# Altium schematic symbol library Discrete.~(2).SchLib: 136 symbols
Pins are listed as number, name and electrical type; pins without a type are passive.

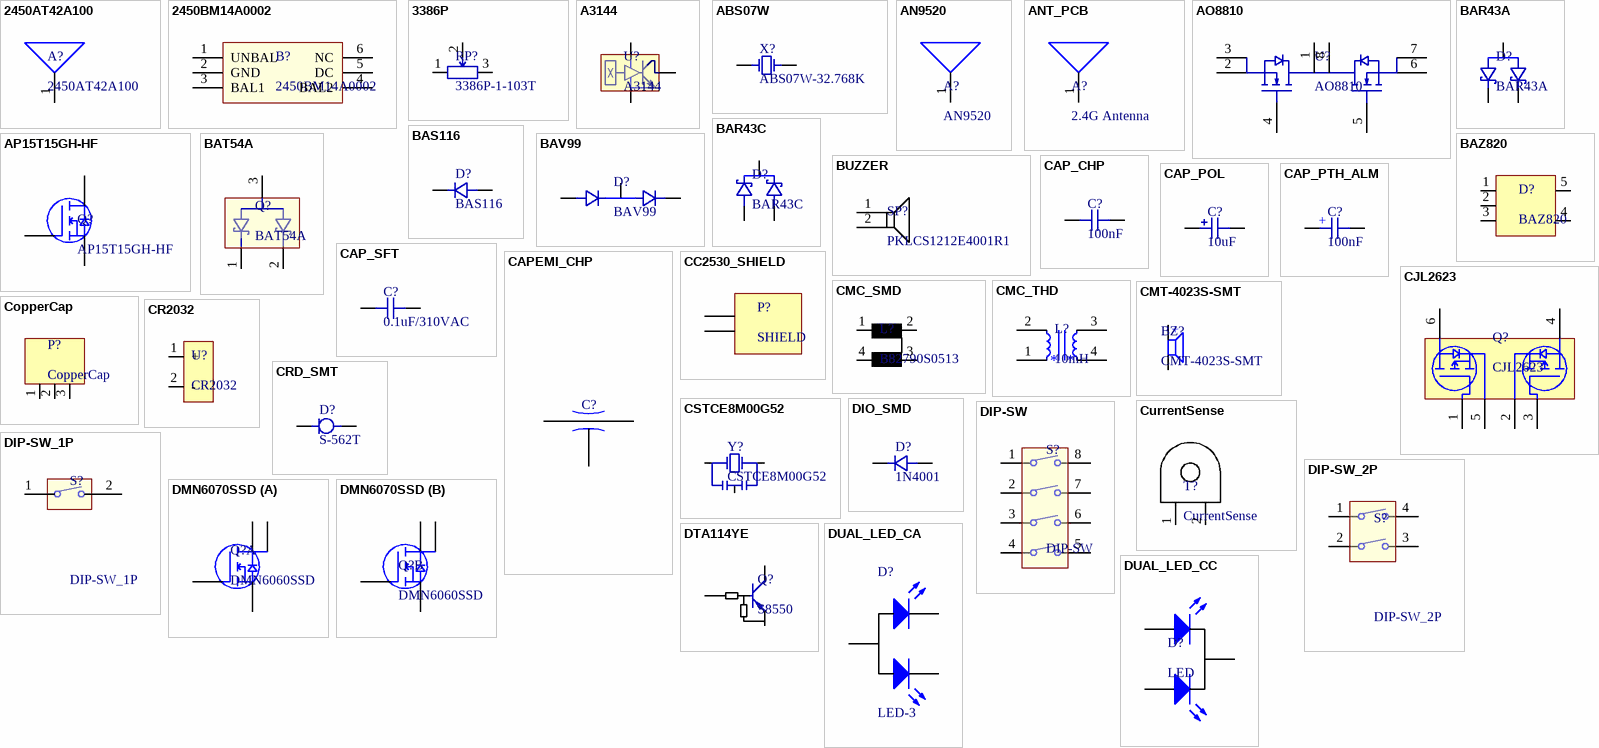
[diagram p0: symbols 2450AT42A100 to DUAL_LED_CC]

## 2450AT42A100
designator A?
2.4G Ceramic Chip Antenna
footprint 2450AT42A100
pins: 1

## 2450BM14A0002
designator B?
Impedance Matched Balun Filter Integrated Passive for   Nordic’s nRF24L01 and nRF24L01+ Chipsets
footprint 2450BM14A0002 (Impedance Matched Balun Filter Integrated Passive for   Nordic’s nRF24L01 and nRF24L01+ Chipsets)
pins: 1 UNBAL, 2 GND (power), 3 BAL1, 4 BAL2, 5 DC (power), 6 NC (power)

## 3386P
designator RP?, comment 3386P-1-103T
3386 - 3/8 ” Square Trimpot® Trimming Potentiometer
footprint 3386P_TRIM_TOP
pins: 1 CCW, 2, 3

## A3144
designator U?
SENSITIVE HALL-EFFECT SWITCHES  FOR HIGH-TEMPERATURE OPERATION
footprint ALLEGRO_HALL
footprint SOT89L (SOT, 3-Leads, Body 4.6 x 2.6 mm, Pitch 1.5mm, IPC High Density)
footprint SOT89M (SOT, 3-Leads, Body 4.6 x 2.6 mm, Pitch 1.5mm, IPC Low Density)
footprint SOT89N (SOT, 3-Leads, Body 4.6 x 2.6 mm, Pitch 1.5mm, IPC Medium Density)
pins: 1 VCC (power), 2 (power), 3 (oc)

## ABS07W
designator X?, comment ABS07W-32.768K
32.768KHZ IoT OPTIMIZED SMD CRYSTAL
pins: 1, 2

## AN9520
designator A?
AN9520 Multilayer Chip Antenn
footprint AN9520_ANTENNA
pins: 1

## ANT_PCB
designator A?, comment 2.4G Antenna  (no BOM)
2.4G Printed Antenna
footprint MIFA_ANTENNA
footprint IFA (Wonderful Antenna Sandbox Electronics Patent Pending)
footprint IFA_CC2530 (2.4GHz Inverted F Antenna)
footprint MIFA_CC2530
pins: 1

## AO8810
designator U?
Common-Drain Dual N-Channel Enhancement Mode Field Effect Transistor
footprint SSOP8_N (3*6.4*1.2mm（长宽高）)
footprint SSOP8_M (3*6.4*1.2mm（长宽高）)
footprint SSOP8_N (3*6.4*1.2mm（长宽高）)
pins: 1 D1/D2, 2 S1, 3 S1, 4 G1, 5 G2, 6 S2 (power), 7 S2 (power), 8 D1/D2

## AP15T15GH-HF
designator Q?
N-CHANNEL ENHANCEMENT MODE   Electronics Corp. POWER MOSFET
footprint TO252-3L (D-PAK, 4-Leads, Body 6.1x6.5mm, Pitch 2.28mm, Lead Span 9.7mm, IPC High Density)
footprint TO252-3M (D-PAK, 4-Leads, Body 6.1x6.5mm, Pitch 2.28mm, Lead Span 9.7mm, IPC Low Density)
footprint TO252-3N (D-PAK, 4-Leads, Body 6.1x6.5mm, Pitch 2.28mm, Lead Span 9.7mm, IPC Medium Density)
pins: 1 G, 3 S, 4 D

## BAR43A
designator D?
Dual Schottky Diodes
footprint SOT23-3L (SOT23, 3-Leads, Body 2.9x1.3mm, Pitch 0.95mm, Lead Span 2.5mm, IPC High Density)
footprint SOT23-3M (SOT23, 3-Leads, Body 2.9x1.3mm, Pitch 0.95mm, Lead Span 2.5mm, IPC Low Density)
footprint SOT23-3N (SOT23, 3-Leads, Body 2.9x1.3mm, Pitch 0.95mm, Lead Span 2.5mm, IPC Medium Density)
pins: 1, 2, 3

## BAR43C
designator D?
Dual Schottky Diodes
footprint SOT23-3L (SOT23, 3-Leads, Body 2.9x1.3mm, Pitch 0.95mm, Lead Span 2.5mm, IPC High Density)
footprint SOT23-3M (SOT23, 3-Leads, Body 2.9x1.3mm, Pitch 0.95mm, Lead Span 2.5mm, IPC Low Density)
footprint SOT23-3N (SOT23, 3-Leads, Body 2.9x1.3mm, Pitch 0.95mm, Lead Span 2.5mm, IPC Medium Density)
pins: 1, 2, 3

## BAS116
designator D?
Low-leakage diode
footprint SOT23-3L (SOT23, 3-Leads, Body 2.9x1.3mm, Pitch 0.95mm, Lead Span 2.5mm, IPC High Density)
footprint SOT23-3M (SOT23, 3-Leads, Body 2.9x1.3mm, Pitch 0.95mm, Lead Span 2.5mm, IPC Low Density)
footprint SOT23-3N (SOT23, 3-Leads, Body 2.9x1.3mm, Pitch 0.95mm, Lead Span 2.5mm, IPC Medium Density)
pins: 1, 3

## BAT54A
designator Q?
Dual common anode chottky barrier rectifier
footprint SOT23-3L (SOT23, 3-Leads, Body 2.9x1.3mm, Pitch 0.95mm, Lead Span 2.5mm, IPC High Density)
footprint SOT23-3M (SOT23, 3-Leads, Body 2.9x1.3mm, Pitch 0.95mm, Lead Span 2.5mm, IPC Low Density)
footprint SOT23-3N (SOT23, 3-Leads, Body 2.9x1.3mm, Pitch 0.95mm, Lead Span 2.5mm, IPC Medium Density)
pins: 1, 2, 3

## BAV99
designator D?
Dual Small Signal Diodes
footprint SOT23-3L (SOT23, 3-Leads, Body 2.9x1.3mm, Pitch 0.95mm, Lead Span 2.5mm, IPC High Density)
footprint SOT23-3M (SOT23, 3-Leads, Body 2.9x1.3mm, Pitch 0.95mm, Lead Span 2.5mm, IPC Low Density)
footprint SOT23-3N (SOT23, 3-Leads, Body 2.9x1.3mm, Pitch 0.95mm, Lead Span 2.5mm, IPC Medium Density)
pins: 1 (power), 2 (power), 3 (power)

## BAZ820
designator D?
Dual Channel ESD Circuit Protector
footprint SOT23-5_L (SOT23, 5-Leads, Body 2.9x1.6mm, Pitch 0.95mm, Lead Span 2.8mm, IPC High Density)
footprint SOT23-5_M (SOT23, 5-Leads, Body 2.9x1.6mm, Pitch 0.95mm, Lead Span 2.8mm, IPC Low Density)
footprint SOT23-5_N (SOT23, 5-Leads, Body 2.9x1.6mm, Pitch 0.95mm, Lead Span 2.8mm, IPC Medium Density)
pins: 1 (power), 2 (power), 3 (power), 4 (power), 5 (power)

## BUZZER
designator SP?, comment PKLCS1212E4001R1
PIEZO BUZZER
footprint BUZZER12X12
footprint TMB12A05 (5V, 12mm, Buzzer)
footprint TMB09A05 (3V, 9mm, Buzzer)
pins: 1, 2

## CAP_CHP
designator C?, comment 100nF
Surface Mount Unpolarized Capacitor
footprint CAPC1608L (Chip Capacitor, Body 1.6x0.8mm, IPC High Density)
footprint CAPC1608M (Chip Capacitor, Body 1.6x0.8mm, IPC Low Density)
footprint CAPC1608N (Chip Capacitor, Body 1.6x0.8mm, IPC Medium Density)
footprint CAPC2012L (Chip Capacitor, Body 2.0x1.3mm, IPC High Density)
footprint CAPC2012M (Chip Capacitor, Body 2.0x1.3mm, IPC Low Density)
footprint CAPC2012N (Chip Capacitor, Body 2.0x1.3mm, IPC Medium Density)
footprint CAPC3216L (Chip Capacitor, Body 3.2x1.6mm, IPC High Density)
footprint CAPC3216M (Chip Capacitor, Body 3.2x1.6mm, IPC Low Density)
footprint CAPC3216N (Chip Capacitor, Body 3.2x1.6mm, IPC Medium Density)
footprint CAPC3225L (Chip Capacitor, Body 3.2x2.5mm, IPC High Density)
footprint CAPC3225M (Chip Capacitor, Body 3.2x2.5mm, IPC Low Density)
footprint CAPC3225N (Chip Capacitor, Body 3.2x2.5mm, IPC Medium Density)
footprint CAPC1005L (Chip Capacitor, Body 1.0x0.5mm, IPC High Density)
footprint CAPC1005M (Chip Capacitor, Body 1.0x0.5mm, IPC Low Density)
footprint CAPC1005N (Chip Capacitor, Body 1.0x0.5mm, IPC Medium Density)
footprint ECHU1608
footprint ECHU2012
footprint ECWU3216
footprint CAPC4532L (Chip Capacitor, Body 4.5x3.2mm, IPC High Density)
footprint CAPC4532M (Chip Capacitor, Body 4.5x3.2mm, IPC Low Density)
footprint CAPC4532N (Chip Capacitor, Body 4.5x3.2mm, IPC Medium Density)
pins: 1, 2

## CAP_POL
designator C?, comment 10uF
Surface Mount Polarized Capacitor
footprint CAPAE660X660L
footprint CAPAE660X660M
footprint CAPAE660X660N
footprint CAPMP3216L (Capacitor, polarized, Molded,  CASE A)
footprint CAPMP3216M (Capacitor, polarized, Molded, CASE A)
footprint CAPMP3216N (Capacitor, polarized, Molded, CASE A)
footprint CAPMP6032M (Capacitor, polarized, Molded, CASE C)
footprint CAPMP6032N (Capacitor, polarized, Molded, CASE C)
footprint CAPMP7343L
footprint CAPMP7343N
footprint CAPAE1350X1350L
footprint CAPAE1350X1350M
footprint CAPAE1350X1350N
footprint CAPAE830X1020L
footprint CAPAE830X1020M
footprint CAPAE830X1020N
footprint EECENOF204RK
footprint CAPMP3528N (Capacitor, polarized, Molded, CASE B)
footprint CAPMP3528M (Capacitor, polarized, Molded, CASE B)
footprint CAPMP3528L (Capacitor, polarized, Molded, CASE B)
footprint CAP_AL_THT (6mm diameter)
footprint CAPAE1030X1020N
footprint CAPMP6032L (Capacitor, polarized, Molded, CASE C)
footprint CAPAE430X540N
footprint CAPAE430X540M
footprint CAPAE430X540L
pins: 1, 2

## CAP_PTH_ALM
designator C?, comment 100nF
Aliuminum Through-hole Capacitor
footprint CAP 1.5*4*8 (脚距1.5mm直径4mm高度8mm)
footprint CAP 1.5*4*8 - BK (脚距1.5mm直径4mm高度8mm)
footprint CAP 1.5*4*8 - GD (脚距1.5mm直径4mm高度8mm)
footprint CAP 1.5*4*8-H (脚距1.5mm直径4mm高度8mm)
footprint CAP 1.5*4*8-H - BK (脚距1.5mm直径4mm高度8mm)
footprint CAP 1.5*4*8-H - GD (脚距1.5mm直径4mm高度8mm)
footprint CAP 2.0*5*11 (脚距2mm直径5mm高度11mm)
footprint CAP 2.0*5*11 - BK (脚距2mm直径5mm高度11mm)
footprint CAP 2.0*5*11 - GD (脚距2mm直径5mm高度11mm)
footprint CAP 2.0*5*11-H (脚距2mm直径5mm高度11mm)
footprint CAP 2.0*5*11-H - BK (脚距2mm直径5mm高度11mm)
footprint CAP 2.0*5*11-H - GD (脚距2mm直径5mm高度11mm)
footprint CAP 2.5*5*11 - BK (脚距2.5mm直径5mm高度11mm)
footprint CAP 2.5*5*11-H - GD (脚距2.5mm直径5mm高度11mm)
footprint CAP 2.5*5*11 - GD (脚距2.5mm直径5mm高度11mm)
footprint CAP 2.5*5*11-H - BK (脚距2.5mm直径5mm高度11mm)
footprint CAP 2.5*5*11-H (脚距2.5mm直径5mm高度11mm)
footprint CAP 3.5*8*11.5 (脚距3.5mm直径8mm高度11.5mm)
footprint CAP 2.5*5*11 (脚距2.5mm直径5mm高度11mm)
footprint CAP 3.5*8*11.5 - BK (脚距3.5mm直径8mm高度11.5mm)
footprint CAP 3.5*8*11.5 - GD (脚距3.5mm直径8mm高度11.5mm)
footprint CAP 3.5*8*11.5-H (脚距3.5mm直径8mm高度11.5mm)
footprint CAP 3.5*8*11.5-H - BK (脚距3.5mm直径8mm高度11.5mm)
footprint CAP 3.5*8*11.5-H - GD (脚距3.5mm直径8mm高度11.5mm)
footprint CAP 5.0*10*12.5 (脚距5mm直径10mm高度12.5mm)
footprint CAP 5.0*10*12.5 - BK (脚距5mm直径10mm高度12.5mm)
footprint CAP 5.0*10*12.5 - GD (脚距5mm直径10mm高度12.5mm)
footprint CAP 5.0*10*12.5-H (脚距5mm直径10mm高度12.5mm)
footprint CAP 5.0*10*12.5-H - BK (脚距5mm直径10mm高度12.5mm)
footprint CAP 5.0*10*12.5-H - GD (脚距5mm直径10mm高度12.5mm)
footprint CAP 5.0*10*16 (脚距5mm直径10mm高度16mm)
footprint CAP 5.0*10*16 - BK (脚距5mm直径10mm高度16mm)
footprint CAP 5.0*10*16 - GD (脚距5mm直径10mm高度16mm)
footprint CAP 5.0*10*20-H (脚距5mm直径10mm高度20mm)
footprint CAP 5.0*10*16-H (脚距5mm直径10mm高度16mm)
footprint CAP 5.0*10*16-H - BK (脚距5mm直径10mm高度16mm)
footprint CAP 5.0*10*16-H - GD (脚距5mm直径10mm高度16mm)
footprint CAP 5.0*10*20-H - BK (脚距5mm直径10mm高度20mm)
footprint CAP 5.0*10*20-H - GD (脚距5mm直径10mm高度20mm)
footprint CAP 5.0*10*20 (脚距5mm直径10mm高度20mm)
footprint CAP 5.0*10*20 - BK (脚距5mm直径10mm高度20mm)
footprint CAP 5.0*10*20 - GD (脚距5mm直径10mm高度20mm)
footprint CAP 5.0*12.5*20 (脚距5mm直径12.5mm高度20mm)
footprint CAP 5.0*12.5*20 - BK (脚距5mm直径12.5mm高度20mm)
footprint CAP 5.0*12.5*20 - GD (脚距5mm直径12.5mm高度20mm)
footprint CAP 5.0*12.5*20-H (脚距5mm直径12.5mm高度20mm)
footprint CAP 5.0*12.5*20-H - BK (脚距5mm直径12.5mm高度20mm)
footprint CAP 5.0*12.5*20-H - GD (脚距5mm直径12.5mm高度20mm)
footprint CAP 5.0*12.5*25 (脚距5mm直径12.5mm高度25mm)
footprint CAP 5.0*12.5*25 - BK (脚距5mm直径12.5mm高度25mm)
footprint CAP 5.0*12.5*25 - GD (脚距5mm直径12.5mm高度25mm)
footprint CAP 5.0*12.5*25-H (脚距5mm直径12.5mm高度25mm)
footprint CAP 5.0*12.5*25-H - BK (脚距5mm直径12.5mm高度25mm)
footprint CAP 5.0*12.5*25-H - GD (脚距5mm直径12.5mm高度25mm)
footprint CAP 7.5*16*25 (脚距7.5mm直径16mm高度25mm)
footprint CAP 7.5*16*25 - BK (脚距7.5mm直径16mm高度25mm)
footprint CAP 7.5*16*25 - GD (脚距7.5mm直径16mm高度25mm)
footprint CAP 7.5*16*25-H (脚距7.5mm直径16mm高度25mm)
footprint CAP 7.5*16*25-H - BK (脚距7.5mm直径16mm高度25mm)
footprint CAP 7.5*16*25-H - GD (脚距7.5mm直径16mm高度25mm)
footprint CAP 7.5*16*31.5 (脚距7.5mm直径16mm高度31.5mm)
footprint CAP 7.5*16*31.5 - BK (脚距7.5mm直径16mm高度31.5mm)
footprint CAP 7.5*16*31.5 - GD (脚距7.5mm直径16mm高度31.5mm)
footprint CAP 7.5*16*31.5-H (脚距7.5mm直径16mm高度31.5mm)
footprint CAP 7.5*16*31.5-H - BK (脚距7.5mm直径16mm高度31.5mm)
footprint CAP 7.5*16*31.5-H - GD (脚距7.5mm直径16mm高度31.5mm)
footprint CAP 7.5*18*35.5 (脚距7.5mm直径18mm高度35.5mm)
footprint CAP 7.5*18*35.5 - BK (脚距7.5mm直径18mm高度35.5mm)
footprint CAP 7.5*18*35.5 - GD (脚距7.5mm直径18mm高度35.5mm)
footprint CAP 7.5*18*35.5-H (脚距7.5mm直径18mm高度35.5mm)
footprint CAP 7.5*18*35.5-H - BK (脚距7.5mm直径18mm高度35.5mm)
footprint CAP 7.5*18*35.5-H - GD (脚距7.5mm直径18mm高度35.5mm)
footprint CAP 10*22*31.5 (脚距10mm直径22mm高度31.5mm)
footprint CAP 10*22*31.5 - BK (脚距10mm直径22mm高度31.5mm)
footprint CAP 10*22*31.5 - GD (脚距10mm直径22mm高度31.5mm)
footprint CAP 10*22*40 (脚距10mm直径22mm高度40mm)
footprint CAP 10*22*40 - BK (脚距10mm直径22mm高度40mm)
footprint CAP 10*22*40 - GD (脚距10mm直径22mm高度40mm)
footprint Model Name (Footprint not found)
pins: A, K

## CAP_SFT
designator C?, comment 0.1uF/310VAC
AC Lines Safty Capacitor
footprint CX 10*13*11 (脚距10mm高13mm厚11mm)
footprint CX 15*18*11 (脚距15mm高18mm厚11mm)
footprint CY 7.5*8*4 (脚距7.5mm，直径8mm，厚4mm)
footprint CY 7.5*10*4 (脚距7.5mm，直径10mm，厚4mm)
footprint CY 7.5*12*5 (脚距7.5mm，直径12mm，厚5mm)
footprint CY 10*14*5 (脚距10mm，直径14mm，厚5mm)
footprint CY 10*16*6 (脚距10mm，直径16mm，厚6mm)
footprint CY 10*18*6 (脚距10mm，直径18mm，厚6mm)
pins: 1, 2

## CAPEMI_CHP
designator C?
EMI suppression filter
footprint CAPEMI1608
pins: 1, 2, 3

## CC2530_SHIELD
designator P?, comment SHIELD
footprint cc2530shield
footprint cc2530shield600slave
pins: 1, 3

## CJL2623
designator Q?
SOT-23-6L Plastic-Encapsulate MOSFETs
footprint SOT23-6_N (SOT23, 6-Leads, Body 2.9x1.6mm, Pitch 0.95mm, Lead Span 2.8mm, IPC Medium Density)
footprint SOT23-6_M (SOT23, 6-Leads, Body 2.9x1.6mm, Pitch 0.95mm, Lead Span 2.8mm, IPC Low Density)
footprint SOT23-6_L (SOT23, 6-Leads, Body 2.9x1.6mm, Pitch 0.95mm, Lead Span 2.8mm, IPC High Density)
pins: 1, 2, 3, 4, 5, 6

## CMC_SMD
designator L?, comment B82790S0513
Common Mode Choke
footprint CMC_SMD
pins: 1, 2, 3, 4

## CMC_THD
designator L?, comment 10mH
Common-mode Choke
footprint CMC_7X8
footprint UU9.8 (17*12*17mm(长宽高）)
footprint UU10.5 (18*16*20mm(长宽高）)
footprint UU16 (22*17.5*23mm(长宽高）)
pins: 1 GND, 2 GND, 3 GND, 4 GND

## CMT-4023S-SMT
designator BZ?
4 mm, 3 Vo-p, 70 dB, Surface Mount (SMT), Magnetic Audio Transducer Buzzer
footprint CMT-4023S-SMT
pins: 1, 2 -

## CopperCap
designator P?
footprint CopperCap
pins: 1, 2, 3

## CR2032
designator U?
CR2032 Battery
footprint CR2032-THD
pins: 1 +, 2 -

## CRD_SMT
designator D?, comment S-562T
Current Regulation Diodes
footprint SOD3716X135L
footprint SOD3716X135M
footprint SOD3716X135N
pins: 1, 2

## CSTCE8M00G52
designator Y?
Ceramic Resonators (CERALOCK®)
footprint CSTCE_G15C
pins: 1, 2, 3

## CurrentSense
designator T?
footprint CURRENT_SENSE
pins: 1, 2

## DIO_SMD
designator D?, comment 1N4001
Surface Mount General Purpose Diode
footprint DIOM5326X230L (Diode with Molded Body, DO-214AC,SMA)
footprint DIOM5326X230M (Diode with Molded Body)
footprint DIOM5326X230N (Diode with Molded Body)
footprint SOD3716X135L
footprint SOD3716X135M
footprint SOD3716X135N
footprint SOD-323 (SOD-323/SC-76; 2 Leads; Body 1.7 x 1.3 mm, (LxW))
footprint DIOMELF3515L (IEC 100H01, SOD-80C)
footprint DIOMELF3515M (IEC 100H01, SOD-80C)
footprint DIOMELF3515N (IEC 100H01, SOD-80C)
footprint DIOM7959X241N (Diode with Molded Body DO-214AB, SMC)
footprint DIOM7959X241M (Diode with Molded Body DO-214AB, SMC)
footprint DIOM7959X241L (Diode with Molded Body DO-214AB, SMC)
footprint DIOM5336X240N (Diode with Molded Body DO-214AA, SMB)
footprint DIOM5336X240M (Diode with Molded Body DO-214AA, SMB)
footprint DIOM5336X240L (Diode with Molded Body DO-214AA, SMB)
footprint SOD2512X100N (SOD Diode: SOD-323)
footprint SOD2512X100M (SOD Diode: SOD-323)
footprint SOD2512X100L (SOD Diode: SOD-323)
pins: 1, 2

## DIP-SW
designator S?
footprint DIP-SW-4P-SIDE
footprint DIP-SW-4P-SMD
pins: 1, 2, 3, 4, 5, 6, 7, 8

## DIP-SW_1P
designator S?
footprint DIP-SW-1P-SMD
footprint DIP-SW-1P-THD
pins: 1, 2

## DIP-SW_2P
designator S?
footprint DIP-SW-2P-SMD
pins: 1, 2, 3, 4

## DMN6070SSD
designator Q?, comment DMN6060SSD
footprint SOIC127P600-8L (SOIC, 8-Leads, Body 4.9x3.9mm, Pitch 1.27mm, IPC High Density)
footprint SOIC127P600-8M (SOIC, 8-Leads, Body 4.9x3.9mm, Pitch 1.27mm, IPC Low Density)
footprint SOIC127P600-8N (SOIC, 8-Leads, Body 4.9x3.9mm, Pitch 1.27mm, IPC Medium Density)
part A pins: 1 S1, 2 G1, 7 D1, 8 D1
part B pins: 3 S2, 4 G2, 5 D2, 6 D2

## DTA114YE
designator Q?, comment S8550
Surface Mount NPN Resistor
footprint SOT23-3L (SOT23, 3-Leads, Body 2.9x1.3mm, Pitch 0.95mm, Lead Span 2.5mm, IPC High Density)
footprint SOT23-3M (SOT23, 3-Leads, Body 2.9x1.3mm, Pitch 0.95mm, Lead Span 2.5mm, IPC Low Density)
footprint SOT23-3N (SOT23, 3-Leads, Body 2.9x1.3mm, Pitch 0.95mm, Lead Span 2.5mm, IPC Medium Density)
pins: 1, 2, 3

## DUAL_LED_CA
designator D?, comment LED-3
Dual LED;Φ3mm.
footprint LED-3PTH
pins: 1 KR, 2 A, 3 KG

## DUAL_LED_CC
designator D?, comment LED
Dual LED Common Cathod
footprint LED-3PTH
pins: 1 KR, 2 A, 3 KG

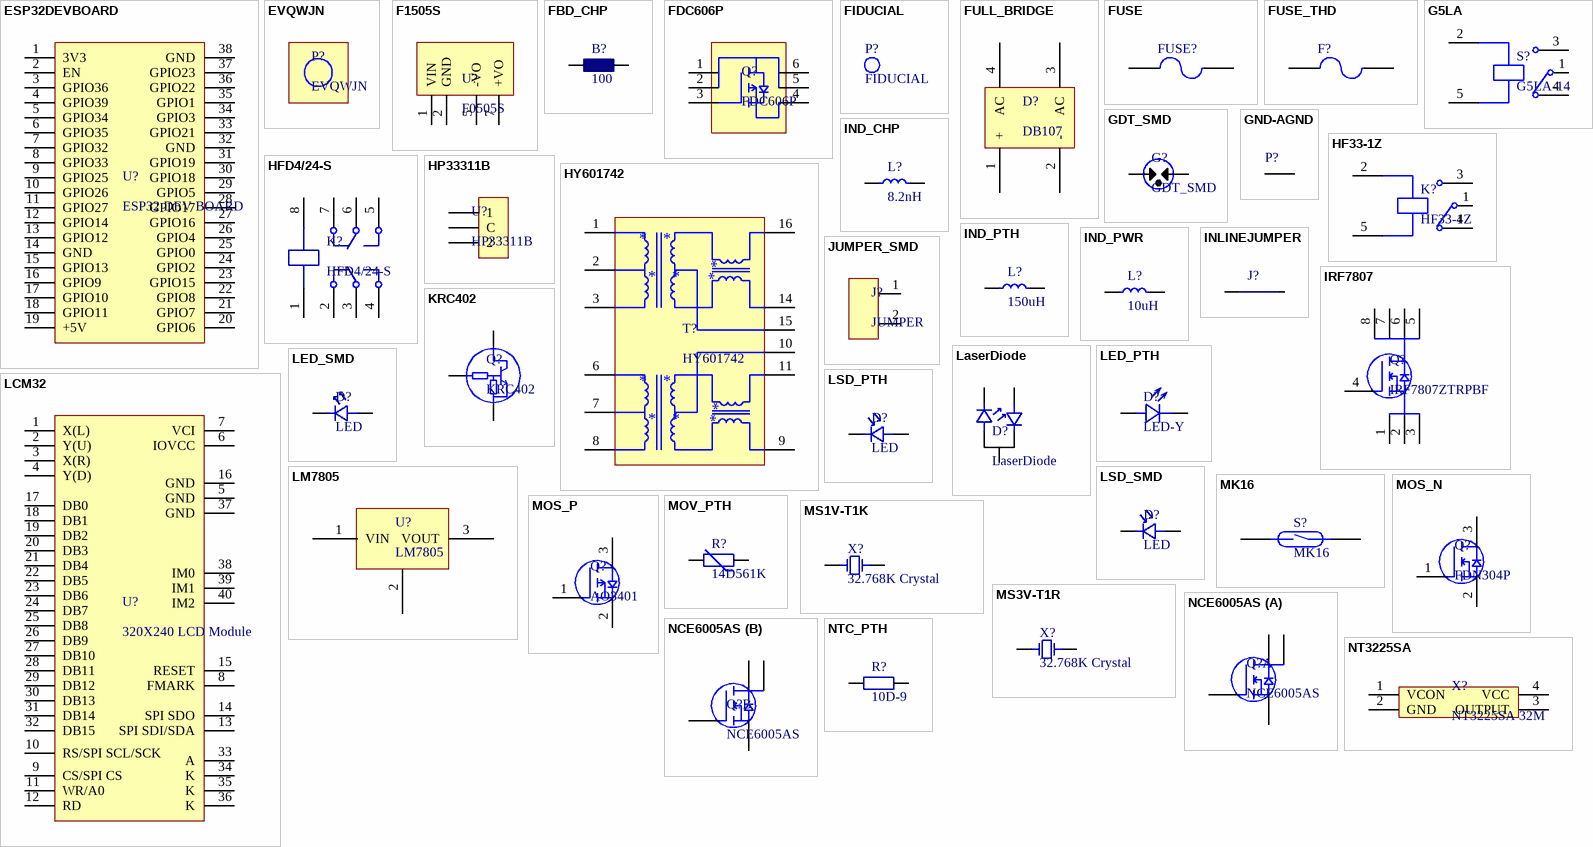
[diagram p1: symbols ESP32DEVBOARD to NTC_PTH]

## ESP32DEVBOARD
designator U?, comment ESP32 DEV BOARD
footprint ESP32DEVBOARD
pins: 1 3V3, 2 EN, 3 GPIO36, 4 GPIO39, 5 GPIO34, 6 GPIO35, 7 GPIO32, 8 GPIO33, 9 GPIO25, 10 GPIO26, 11 GPIO27, 12 GPIO14, 13 GPIO12, 14 GND, 15 GPIO13, 16 GPIO9, 17 GPIO10, 18 GPIO11, 19 +5V, 20 GPIO6, 21 GPIO7, 22 GPIO8, 23 GPIO15, 24 GPIO2, 25 GPIO0, 26 GPIO4, 27 GPIO16, 28 GPIO17, 29 GPIO5, 30 GPIO18, 31 GPIO19, 32 GND, 33 GPIO21, 34 GPIO3, 35 GPIO1, 36 GPIO22, 37 GPIO23, 38 GND

## EVQWJN
designator P?
Jog Ball
footprint EVQWJN (JOGBALL)

## F1505S
designator U?, comment F0505S
Isolated DC-DC Power Supply Module
footprint F1505S
pins: 1 VIN, 2 GND, 5 -VO, 7 +VO

## FBD_CHP
designator B?, comment 100
Surface Mount Ferrite Bead
footprint FBDC1005L (Ferrite Bead, Body 1.1x0.5mm, IPC High Density)
footprint FBDC1005M (Ferrite Bead, Body 1.1x0.5mm, IPC Low Density)
footprint FBDC1005N (Ferrite Bead, Body 1.1x0.5mm, IPC Medium Density)
footprint FBDC1608L (Ferrite Bead, Body 1.6x0.8mm, IPC High Density)
footprint FBDC1608M (Ferrite Bead, Body 1.6x0.8mm, IPC Low Density)
footprint FBDC1608N (Ferrite Bead, Body 1.6x0.8mm, IPC Medium Density)
footprint FBDC2012L (Ferrite Bead, Body 2.0x1.3mm, IPC High Density)
footprint FBDC2012M (Ferrite Bead, Body 2.0x1.3mm, IPC Low Density)
footprint FBDC2012N (Ferrite Bead, Body 2.0x1.3mm, IPC Medium Density)
footprint FBDC3216L (Ferrite Bead, Body 3.2x1.6mm, IPC High Density)
footprint FBDC3216M (Ferrite Bead, Body 3.2x1.6mm, IPC Low Density)
footprint FBDC3216N (Ferrite Bead, Body 3.2x1.6mm, IPC Medium Density)
pins: 1, 2

## FDC606P
designator Q?
P-Channel 1.8V Specified PowerTrench MOSFET
footprint SOT23-6_L (SOT23, 6-Leads, Body 2.9x1.6mm, Pitch 0.95mm, Lead Span 2.8mm, IPC High Density)
footprint SOT23-6_M (SOT23, 6-Leads, Body 2.9x1.6mm, Pitch 0.95mm, Lead Span 2.8mm, IPC Low Density)
footprint SOT23-6_N (SOT23, 6-Leads, Body 2.9x1.6mm, Pitch 0.95mm, Lead Span 2.8mm, IPC Medium Density)
pins: 1, 2, 3, 4, 5, 6

## FIDUCIAL
designator P?  (no BOM)
SMT Fiducial
footprint XH2.54-12P_H (接插件，12P)
footprint Fiducial

## FULL_BRIDGE
designator D?, comment DB107
Full brigde
footprint RCT_BRIDGE
pins: 1 +, 2 -, 3 AC, 4 AC

## FUSE
designator FUSE?, comment 500mA  (value not drawn)
500mA Resetable Fuse
footprint FUSE3216N (Fuse, Body 3.2x1.6mm, IPC Medium Density)
footprint FUSE3216M (Fuse, Body 3.2x1.6mm, IPC Low Density)
footprint FUSE3216L (Fuse, Body 3.2x1.6mm, IPC High Density)
footprint FUSE4532L
footprint FUSE4532M
footprint FUSE4532N
footprint TE5 (TE5 Time-Lag Fuse)
pins: 1, 2

## FUSE_THD
designator F?
500mA Resetable Fuse
footprint WH250-120
pins: 1, 2

## G5LA
designator S?, comment G5LA-14
Single Pole Double Throw Relay
footprint G5LA
pins: 1, 2, 3, 4, 5

## GDT_SMD
designator G?
SMD Gas Discharging Tube
footprint GDT
pins: 1, 2

## GND-AGND
designator P?, comment SHORT  (value not drawn)  (no BOM)
footprint GND_AGND
pins: 1, 2

## HF33-1Z
designator K?
Single Pole Double Throw Relay
footprint HF33F-1Z
pins: 1, 2, 3, 4, 5

## HFD4/24-S
designator K?
Subminiature Signal Relay
footprint HFD4-S
pins: 1, 2, 3, 4, 5, 6, 7, 8

## HP33311B
designator U?
RF COXIAL SWITCH
footprint HP33311B
pins: 1, 2, C

## HY601742
designator T?
Magnetics Modules with PoE capability
footprint HY601742
pins: 1, 2, 3, 6, 7, 8, 9, 10, 11, 14, 15, 16

## IND_CHP
designator L?, comment 8.2nH
Chip Inductor
footprint INDC1005L (Chip Inductor, Body 1.0x0.5mm, IPC High Density)
footprint INDC1005M (Chip Inductor, Body 1.0x0.5mm, IPC Low Density)
footprint INDC1005N (Chip Inductor, Body 1.0x0.5mm, IPC Medium Density)
footprint INDC3216N (Chip Inductor, Body 3.2x1.6mm, IPC Medium Density)
footprint INDC3216L (Chip Inductor, Body 3.2x1.6mm, IPC High Density)
footprint INDC3216M (Chip Inductor, Body 3.2x1.6mm, IPC Low Density)
footprint INDC1608L (Chip Inductor, Body 1.6x0.8mm, IPC High Density)
footprint INDC1608M (Chip Inductor, Body 1.6x0.8mm, IPC Low Density)
footprint INDC1608N (Chip Inductor, Body 1.6x0.8mm, IPC Medium Density)
footprint INDC3225N (Chip Inductor, Body 3.2x2.5mm, IPC Medium Density)
footprint INDC3225M (Chip Inductor, Body 3.2x2.5mm, IPC Low Density)
footprint INDC3225L (Chip Inductor, Body 3.2x2.5mm, IPC High Density)
pins: 1, 2

## IND_PTH
designator L?, comment 150uH
Through Hole Inductor
footprint PK0406 (2*5*8mm(脚距，直径，高）)
footprint PK0608 (2.5*7*10mm(脚距，直径，高）)
footprint PK0810 (5*9*12mm(脚距，直径，高）)
footprint PK0912 (6*10*14mm(脚距，直径，高）)
footprint PK1012 (6*11*14mm(脚距，直径，高）)
footprint PK1415 (7.5*15*17mm(脚距，直径，高）)
footprint PK1618 (12.5*17*20mm(脚距，直径，高）)
footprint PK1818 (15*19*20mm(脚距，直径，高）)
pins: 1, 2

## IND_PWR
designator L?, comment 10uH
Power Inductor
footprint Inductor
footprint PWRIND_SWPA3015S (Sunloardic SMT Inductor SWPA3015S Series)
footprint CDRH74 (SMD Power Inductor 7.5x7.5x4.5mm)
footprint PWRIND_SWRH2D14R
footprint PWRIND_SDRH104R
footprint PWRIND_SWRH4D28S
footprint PWRIND_SWPA252012S
footprint PWRIND_SWRH5D28S
footprint PWRIND_WE-LHMI
footprint LPS3015
footprint PWRIND_0630
footprint PWRIND_0520
pins: 1, 2

## INLINEJUMPER
designator J?  (value not drawn)
footprint JMPINLINE12MIL
pins: 1, 1

## IRF7807
designator Q?, comment IRF7807ZTRPBF
N-Channel MOSFET
footprint SOIC127P600-8L (SOIC, 8-Leads, Body 4.9x3.9mm, Pitch 1.27mm, IPC High Density)
footprint SOIC127P600-8M (SOIC, 8-Leads, Body 4.9x3.9mm, Pitch 1.27mm, IPC Low Density)
footprint SOIC127P600-8N (SOIC, 8-Leads, Body 4.9x3.9mm, Pitch 1.27mm, IPC Medium Density)
pins: 1, 2, 3, 4, 5, 6, 7, 8

## JUMPER_SMD
designator J?, comment JUMPER  (no BOM)
SMD JUMPER
footprint JUMPER_127X127 (1mmX1mm Jumper)
footprint SOLDER_JUMPER
pins: 1, 2

## KRC402
designator Q?
Resistor-equipped Transistor
footprint SOT323-3BL (SOT23, 3-Leads, Body 2x1.25mm, Pitch 0.65mm, Lead Span 2.1mm, IPC High Density)
footprint SOT323-3BM (SOT23, 3-Leads, Body 2x1.25mm, Pitch 0.65mm, Lead Span 2.1mm, IPC Low Density)
footprint SOT323-3BN (SOT23, 3-Leads, Body 2x1.25mm, Pitch 0.65mm, Lead Span 2.1mm, IPC Medium Density)
pins: 1, 2, 3

## LaserDiode
designator D?
Surface Mount LED
footprint LaserDiode5.6
pins: 1, 2, 3

## LCM32
designator U?, comment 320X240 LCD Module
footprint LCM32
pins: 1 X(L), 2 Y(U), 3 X(R), 4 Y(D), 5 GND, 6 IOVCC, 7 VCI, 8 FMARK, 9 CS/SPI CS, 10 RS/SPI SCL/SCK, 11 WR/A0, 12 RD, 13 SPI SDI/SDA, 14 SPI SDO, 15 RESET, 16 GND, 17 DB0, 18 DB1, 19 DB2, 20 DB3, 21 DB4, 22 DB5, 23 DB6, 24 DB7, 25 DB8, 26 DB9, 27 DB10, 28 DB11, 29 DB12, 30 DB13, 31 DB14, 32 DB15, 33 A, 34 K, 35 K, 36 K, 37 GND, 38 IM0, 39 IM1, 40 IM2

## LED_PTH
designator D?, comment LED-Y
footprint LED-2-PTH
pins: 1, 2

## LED_SMD
designator D?, comment LED
Surface Mount LED
footprint LEDC1608L (Chip LED, Body 1.6x0.8mm, IPC High Density)
footprint LEDC1608M (Chip LED, Body 1.6x0.8mm, IPC Low Density)
footprint LEDC1608N (Chip LED, Body 1.6x0.8mm, IPC Medium Density)
footprint LEDC2012L (Chip LED, Body 2.0x1.3mm, IPC High Density)
footprint LEDC2012M (LED Resistor, Body 2.0x1.3mm, IPC Low Density)
footprint LEDC2012N (Chip LED, Body 2.0x1.3mm, IPC Medium Density)
footprint LED3528
footprint LEDC1005L (Chip LED, Body 1.1x0.5mm, IPC High Density)
footprint LEDC1005M (Chip LED, Body 1.1x0.5mm, IPC Low Density)
footprint LEDC1005N (Chip LED,  Body 1.1x0.5mm, IPC Medium Density)
pins: 1, 2

## LM7805
designator U?
5V 3-terminal Voltage Regulator
pins: 1 VIN, 2 GND, 3 VOUT

## LSD_PTH
designator D?, comment LED
Surface Mount LED
footprint LED-2-PTH
pins: 1, 2

## LSD_SMD
designator D?, comment LED
Surface Mount LED
footprint LEDC1608L (Chip LED, Body 1.6x0.8mm, IPC High Density)
footprint LEDC1608M (Chip LED, Body 1.6x0.8mm, IPC Low Density)
footprint LEDC1608N (Chip LED, Body 1.6x0.8mm, IPC Medium Density)
footprint LEDC2012L (Chip LED, Body 2.0x1.3mm, IPC High Density)
footprint LEDC2012M (LED Resistor, Body 2.0x1.3mm, IPC Low Density)
footprint LEDC2012N (Chip LED, Body 2.0x1.3mm, IPC Medium Density)
footprint LED3528
pins: 1, 2

## MK16
designator S?
MK16 Reed Switch
footprint MK-16
pins: 1, 2

## MOS_N
designator Q?, comment FDN304P
N-Channel MOSFET
footprint SOT23-3L (SOT23, 3-Leads, Body 2.9x1.3mm, Pitch 0.95mm, Lead Span 2.5mm, IPC High Density)
footprint SOT23-3M (SOT23, 3-Leads, Body 2.9x1.3mm, Pitch 0.95mm, Lead Span 2.5mm, IPC Low Density)
footprint SOT23-3N (SOT23, 3-Leads, Body 2.9x1.3mm, Pitch 0.95mm, Lead Span 2.5mm, IPC Medium Density)
footprint TO252-3L (D-PAK, 4-Leads, Body 6.1x6.5mm, Pitch 2.28mm, Lead Span 9.7mm, IPC High Density)
footprint TO252-3M (D-PAK, 4-Leads, Body 6.1x6.5mm, Pitch 2.28mm, Lead Span 9.7mm, IPC Low Density)
footprint TO252-3N (D-PAK, 4-Leads, Body 6.1x6.5mm, Pitch 2.28mm, Lead Span 9.7mm, IPC Medium Density)
footprint X2-DFN1006-3
pins: 1, 2, 3

## MOS_P
designator Q?, comment AO3401
P-Channel MOSFET
footprint SOT23-3L (SOT23, 3-Leads, Body 2.9x1.3mm, Pitch 0.95mm, Lead Span 2.5mm, IPC High Density)
footprint SOT23-3M (SOT23, 3-Leads, Body 2.9x1.3mm, Pitch 0.95mm, Lead Span 2.5mm, IPC Low Density)
footprint SOT23-3N (SOT23, 3-Leads, Body 2.9x1.3mm, Pitch 0.95mm, Lead Span 2.5mm, IPC Medium Density)
footprint SOT346-3BL (SOT346, 3-Leads, Body 2.9x1.5mm, Pitch 0.95mm, Lead Span 2.8mm - Alternate Lead Configuration, IPC High Density)
footprint SOT346-3BM (SOT346, 3-Leads, Body 2.9x1.5mm, Pitch 0.95mm, Lead Span 2.8mm - Alternate Lead Configuration, IPC Low Density)
footprint SOT346-3BN (SOT346, 3-Leads, Body 2.9x1.5mm, Pitch 0.95mm, Lead Span 2.8mm - Alternate Lead Configuration, IPC Medium Density)
footprint TO252-3N (D-PAK, 4-Leads, Body 6.1x6.5mm, Pitch 2.28mm, Lead Span 9.7mm, IPC Medium Density)
footprint TO252-3M (D-PAK, 4-Leads, Body 6.1x6.5mm, Pitch 2.28mm, Lead Span 9.7mm, IPC Low Density)
footprint TO252-3L (D-PAK, 4-Leads, Body 6.1x6.5mm, Pitch 2.28mm, Lead Span 9.7mm, IPC High Density)
pins: 1, 2, 3

## MOV_PTH
designator R?, comment 14D561K
MOV Resistor
footprint MOV_14
footprint MOV_20
pins: 1, 2

## MS1V-T1K
designator X?, comment 32.768K Crystal
Tuning Fork Crystal
footprint MS1V-T1K
pins: 1, 2, 3 (power) hidden to GND

## MS3V-T1R
designator X?, comment 32.768K Crystal
Tuning Fork Crystal
footprint MS3V-T1R
pins: 1, 2, 3 (power) hidden to GND

## NCE6005AS
designator Q?
footprint SOIC127P600-8L (SOIC, 8-Leads, Body 4.9x3.9mm, Pitch 1.27mm, IPC High Density)
footprint SOIC127P600-8M (SOIC, 8-Leads, Body 4.9x3.9mm, Pitch 1.27mm, IPC Low Density)
footprint SOIC127P600-8N (SOIC, 8-Leads, Body 4.9x3.9mm, Pitch 1.27mm, IPC Medium Density)
part A pins: 1 S2, 2 G2, 7 D2, 8 D2
part B pins: 3 S1, 4 G1, 5 D1, 6 D1

## NT3225SA
designator X?, comment NT3225SA 32M
Temperature Compensated Crystal Oscillator
footprint OSCCC250X320X100M
footprint OSCCC250X320X100L
footprint OSCCC250X320X100N
pins: 1 VCON, 2 GND, 3 OUTPUT, 4 VCC

## NTC_PTH
designator R?, comment 10D-9
footprint NTC_7.5mm
pins: 1, 2

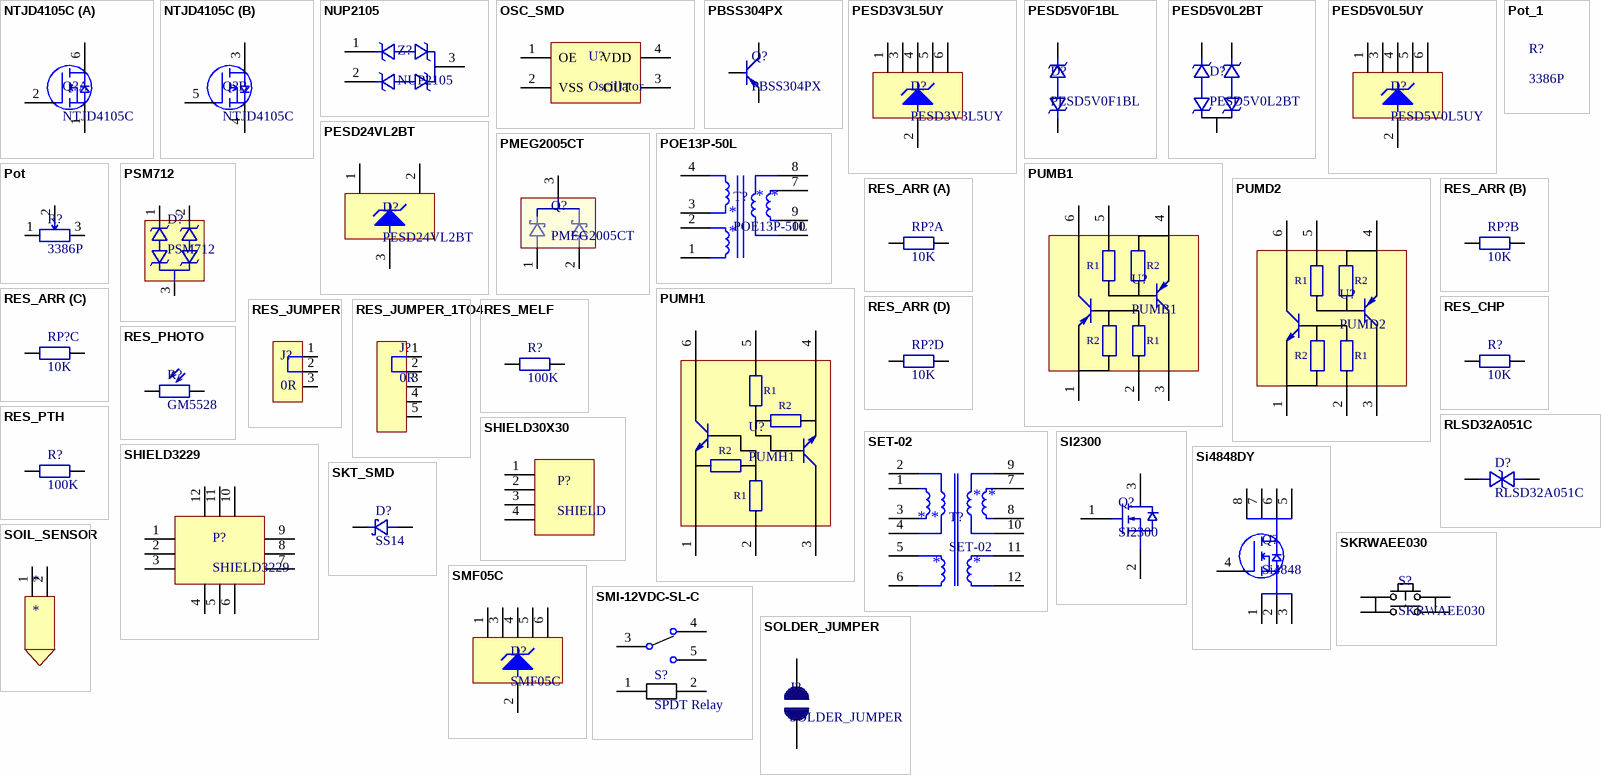
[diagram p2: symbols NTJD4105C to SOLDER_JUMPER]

## NTJD4105C
designator Q?
SMALL SIGNAL MOSFET
footprint SOT363-6L (SOT363, 6-Leads, Body 2x1.3mm, Pitch 0.65mm, Lead Span 2.1mm, IPC High Density)
footprint SOT363-6M
footprint SOT363-6N (SOT363, 6-Leads, Body 2x1.3mm, Pitch 0.65mm, Lead Span 2.1mm, IPC Medium Density)
part A pins: 1, 2, 6
part B pins: 3, 4, 5

## NUP2105
designator Z?
ESD Protection for High-speed CAN Bus
footprint SOT23-3L (SOT23, 3-Leads, Body 2.9x1.3mm, Pitch 0.95mm, Lead Span 2.5mm, IPC High Density)
footprint SOT23-3M (SOT23, 3-Leads, Body 2.9x1.3mm, Pitch 0.95mm, Lead Span 2.5mm, IPC Low Density)
footprint SOT23-3N (SOT23, 3-Leads, Body 2.9x1.3mm, Pitch 0.95mm, Lead Span 2.5mm, IPC Medium Density)
pins: 1, 2, 3

## OSC_SMD
designator U?, comment Oscillator
footprint OSCSC508P500X700X160-4L
footprint OSCSC508P500X700X160-4M
footprint OSCSC508P500X700X160-4N
pins: 1 OE, 2 VSS, 3 OUT, 4 VDD

## PBSS304PX
designator Q?
60 V, 4.2 A PNP low VCEsat (BISS) transistor
footprint SOT89L (SOT, 3-Leads, Body 4.6 x 2.6 mm, Pitch 1.5mm, IPC High Density)
footprint SOT89M (SOT, 3-Leads, Body 4.6 x 2.6 mm, Pitch 1.5mm, IPC Low Density)
footprint SOT89N (SOT, 3-Leads, Body 4.6 x 2.6 mm, Pitch 1.5mm, IPC Medium Density)
pins: 1, 2, 3

## PESD3V3L5UY
designator D?
5-Line Transient Voltage Suppressor Array
footprint SOT363-6L (SOT363, 6-Leads, Body 2x1.3mm, Pitch 0.65mm, Lead Span 2.1mm, IPC High Density)
footprint SOT363-6M
footprint SOT363-6N (SOT363, 6-Leads, Body 2x1.3mm, Pitch 0.65mm, Lead Span 2.1mm, IPC Medium Density)
pins: 1 NC, 2 NC, 3 NC, 4 NC, 5 NC, 6 NC

## PESD5V0F1BL
designator D?
Low capacitance single bidirectional ESD protection diodes in SOT23
footprint SOD-323 (SOD-323/SC-76; 2 Leads; Body 1.7 x 1.3 mm, (LxW))
pins: 1, 2

## PESD5V0L2BT
designator D?
Low capacitance double bidirectional ESD protection diodes in SOT23
footprint SOT23-3L (SOT23, 3-Leads, Body 2.9x1.3mm, Pitch 0.95mm, Lead Span 2.5mm, IPC High Density)
footprint SOT23-3M (SOT23, 3-Leads, Body 2.9x1.3mm, Pitch 0.95mm, Lead Span 2.5mm, IPC Low Density)
footprint SOT23-3N (SOT23, 3-Leads, Body 2.9x1.3mm, Pitch 0.95mm, Lead Span 2.5mm, IPC Medium Density)
pins: 1, 2, 3

## PESD5V0L5UY
designator D?
5-Line Transient Voltage Suppressor Array
footprint SOT363-6L (SOT363, 6-Leads, Body 2x1.3mm, Pitch 0.65mm, Lead Span 2.1mm, IPC High Density)
footprint SOT363-6M
footprint SOT363-6N (SOT363, 6-Leads, Body 2x1.3mm, Pitch 0.65mm, Lead Span 2.1mm, IPC Medium Density)
pins: 1 NC, 2 NC, 3 NC, 4 NC, 5 NC, 6 NC

## PESD24VL2BT
designator D?
2-Line Transient Voltage Suppressor Array
footprint SOT23-3L (SOT23, 3-Leads, Body 2.9x1.3mm, Pitch 0.95mm, Lead Span 2.5mm, IPC High Density)
footprint SOT23-3M (SOT23, 3-Leads, Body 2.9x1.3mm, Pitch 0.95mm, Lead Span 2.5mm, IPC Low Density)
footprint SOT23-3N (SOT23, 3-Leads, Body 2.9x1.3mm, Pitch 0.95mm, Lead Span 2.5mm, IPC Medium Density)
pins: 1 LINE1, 2 LINE2, 3 COM

## PMEG2005CT
designator Q?
Dual common cathode MEGA schottky barrier rectifier
footprint SOT23-3L (SOT23, 3-Leads, Body 2.9x1.3mm, Pitch 0.95mm, Lead Span 2.5mm, IPC High Density)
footprint SOT23-3M (SOT23, 3-Leads, Body 2.9x1.3mm, Pitch 0.95mm, Lead Span 2.5mm, IPC Low Density)
footprint SOT23-3N (SOT23, 3-Leads, Body 2.9x1.3mm, Pitch 0.95mm, Lead Span 2.5mm, IPC Medium Density)
pins: 1, 2, 3

## POE13P-50L
designator T?
Flyback Transformers
footprint POE13P
pins: 1, 2, 3, 4, 7, 8, 9, 10

## Pot
designator R?, comment 3386P
Trim pot
footprint 3362_Trim_Top
footprint EVM3Y
footprint 3224W (3224 - 4 mm SMD Trimpot?)
pins: 1, 2, 3

## Pot_1
designator R?, comment 3386P
footprint 3362_Trim_Top
footprint EVM3Y
footprint 3224W (3224 - 4 mm SMD Trimpot?)

## PSM712
designator D?
600Watt TVS ARRAY
footprint SOT23-3L (SOT23, 3-Leads, Body 2.9x1.3mm, Pitch 0.95mm, Lead Span 2.5mm, IPC High Density)
footprint SOT23-3M (SOT23, 3-Leads, Body 2.9x1.3mm, Pitch 0.95mm, Lead Span 2.5mm, IPC Low Density)
footprint SOT23-3N (SOT23, 3-Leads, Body 2.9x1.3mm, Pitch 0.95mm, Lead Span 2.5mm, IPC Medium Density)
pins: 1, 2, 3

## PUMB1
designator U?
PNP/PNP resistor-equipped transistors; R1 = 22 k?, R2 = 22 k?
footprint SOT363-6L (SOT363, 6-Leads, Body 2x1.3mm, Pitch 0.65mm, Lead Span 2.1mm, IPC High Density)
footprint SOT363-6M
footprint SOT363-6N (SOT363, 6-Leads, Body 2x1.3mm, Pitch 0.65mm, Lead Span 2.1mm, IPC Medium Density)
pins: 1, 2, 3, 4, 5, 6

## PUMD2
designator U?
NPN/PNP resistor-equipped transistors; R1 = 22 k, R2 = 22 k
footprint SOT363-6L (SOT363, 6-Leads, Body 2x1.3mm, Pitch 0.65mm, Lead Span 2.1mm, IPC High Density)
footprint SOT363-6M
footprint SOT363-6N (SOT363, 6-Leads, Body 2x1.3mm, Pitch 0.65mm, Lead Span 2.1mm, IPC Medium Density)
pins: 1, 2, 3, 4, 5, 6

## PUMH1
designator U?
NPN/NPN resistor-equipped transistors; R1 = 22 k?, R2 = 22 k?
footprint SOT363-6L (SOT363, 6-Leads, Body 2x1.3mm, Pitch 0.65mm, Lead Span 2.1mm, IPC High Density)
footprint SOT363-6M
footprint SOT363-6N (SOT363, 6-Leads, Body 2x1.3mm, Pitch 0.65mm, Lead Span 2.1mm, IPC Medium Density)
pins: 1, 2, 3, 4, 5, 6

## RES_ARR
designator RP?, comment 10K
0603X4 Resistor Pack
footprint RESCAXS80P150X320X45-8L (Resistor Array 0603X4 S-VERSION)
footprint RESCAXS80P150X320X45-8M (Resistor Array 0603X4 S-VERSION)
footprint RESCAXS80P150X320X45-8N (Resistor Array 0603X4 S-VERSION)
part A pins: 1, 8
part B pins: 2, 7
part C pins: 3, 6
part D pins: 4, 5

## RES_CHP
designator R?, comment 10K
Surface Mount Resistor
footprint RESC2012L (Chip Resistor, Body 2.0x1.3mm, IPC High Density)
footprint RESC2012M (Chip Resistor, Body 2.0x1.3mm, IPC Low Density)
footprint RESC2012N (Chip Resistor, Body 2.0x1.3mm, IPC Medium Density)
footprint RESC1608L (Chip Resistor, Body 1.6x0.8mm, IPC High Density)
footprint RESC1608M (Chip Resistor, Body 1.6x0.8mm, IPC Low Density)
footprint RESC1608N (Chip Resistor, Body 1.6x0.8mm, IPC Medium Density)
footprint RESC3216L (Chip Resistor, Body 3.2x1.6mm, IPC High Density)
footprint RESC3216M (Chip Resistor, Body 3.2x1.6mm, IPC Low Density)
footprint RESC3216N (Chip Resistor, Body 3.2x1.6mm, IPC Medium Density)
footprint RESC1005L (Chip Resistor, Body 1.1x0.5mm, IPC High Density)
footprint RESC1005M (Chip Resistor, Body 1.1x0.5mm, IPC Low Density)
footprint RESC1005N (Chip Resistor, Body 1.1x0.5mm, IPC Medium Density)
footprint RESC4532L (Chip Resistor, Body 4.5x3.2mm, IPC High Density)
footprint RESC4532M (Chip Resistor, Body 4.5x3.2mm, IPC Low Density)
footprint RESC4532N (Chip Resistor, Body 4.5x3.2mm, IPC Medium Density)
footprint RESC3225L (Chip Resistor, Body 3.2x2.5mm, IPC High Density)
footprint RESC3225M (Chip Resistor, Body 3.2x2.5mm, IPC Low Density)
footprint RESC3225N (Chip Resistor, Body 3.2x2.5mm, IPC Medium Density)
footprint RESC6332N (Chip Resistor, Body 6.3x3.2mm, IPC Medium Density)
footprint RESC6332M (Chip Resistor, Body 6.3x3.2mm, IPC Low Density)
footprint RESC6332L (Chip Resistor, Body 6.3x3.2mm, IPC High Density)
pins: 1, 2

## RES_JUMPER
designator J?, comment 0R
footprint RESJUMPER2012M
footprint RESJUMPER2012N
footprint RESJUMPER3216N (Chip Resistor, Body 3.2x1.6mm, IPC Medium Density)
footprint RESJUMPER1608N (Chip Resistor, Body 1.6x0.8mm, IPC Medium Density)
footprint JUMPER_1TO2 (1mmX1mm Jumper)
pins: 1, 2, 3

## RES_JUMPER_1TO4
designator J?, comment 0R
footprint RESCJUMPER
footprint RESCJUMPER_ROTATE
pins: 1, 2, 3, 4 (power), 5 (power)

## RES_MELF
designator R?, comment 100K
MELF Resistor
footprint MELF-REISTOR-12mm
footprint MELF0204 (MELF Resistor 3.6mmX1.4mm)
footprint MELF0207 (MELF Resistor 5.8mmX2.2mm)
pins: 1, 2

## RES_PHOTO
designator R?, comment GM5528
footprint GM5528
pins: 1, 2

## RES_PTH
designator R?, comment 100K
Through Hole Resistor
footprint RS 1/2W (直插色环电阻，脚距12.5mm，直径3mm)
footprint RS 1/2W-V4 (直插色环电阻，脚距4mm，直径3mm)
footprint RS 1/4W (直插色环电阻，脚距9mm，直径2.3mm)
footprint RS 1/4W-V3 (直插色环电阻，脚距3mm，直径2.3mm)
footprint RS 1/8W (直插色环电阻，脚距6mm，直径1.5mm)
footprint RS 1/8W-V2 (直插色环电阻，脚距2mm，直径1.5mm)
footprint RS 1W (直插色环电阻，脚距15mm，直径4mm)
footprint RS 1W-F5 (直插色环电阻，脚距15mm，直径4mm，浮空5mm)
footprint RS 1W-V5 (直插色环电阻，脚距5mm，直径4mm)
footprint RS 2W (直插色环电阻，脚距20mm，直径5mm)
footprint RS 2W-F5 (直插色环电阻，脚距20mm，直径5mm，浮空5mm)
footprint RS 2W-V6 (直插色环电阻，脚距6mm，直径5mm)
footprint RS 3W (直插色环电阻，脚距25mm，直径6mm)
footprint RS 3W-F5 (直插色环电阻，脚距25mm，直径6mm，浮空5mm)
footprint RS 3W-V7 (直插色环电阻，脚距7mm，直径6mm)
footprint RS 5W (直插色环电阻，脚距30mm，直径8mm)
footprint RS 5W-F5 (直插色环电阻，脚距30mm，直径8mm，浮空5mm)
footprint RS 5W-V8 (直插色环电阻，脚距8mm，直径8mm)
pins: 1, 2

## RLSD32A051C
designator D?
ESD Diode
footprint SOD-323 (SOD-323/SC-76; 2 Leads; Body 1.7 x 1.3 mm, (LxW))
pins: 1, 2

## SET-02
designator T?
Flyback Transformer
footprint EFD20-6P-SMD
pins: 1, 2, 3, 4, 5, 6, 7, 8, 9, 10, 11, 12

## SHIELD30X30
designator P?, comment SHIELD
footprint SHIELD30X30
pins: 1, 2, 3, 4

## SHIELD3229
designator P?
footprint SHIELD3229
pins: 1, 2, 3, 4, 5, 6, 7, 8, 9, 10, 11, 12

## SI2300
designator Q?
N-Channel MOSFET
pins: 1 G, 2 S1, 3 D

## Si4848DY
designator Q?, comment Si4848
N-Channel MOSFET
footprint SOIC127P600-8L (SOIC, 8-Leads, Body 4.9x3.9mm, Pitch 1.27mm, IPC High Density)
footprint SOIC127P600-8M (SOIC, 8-Leads, Body 4.9x3.9mm, Pitch 1.27mm, IPC Low Density)
footprint SOIC127P600-8N (SOIC, 8-Leads, Body 4.9x3.9mm, Pitch 1.27mm, IPC Medium Density)
pins: 1, 2, 3, 4, 5, 6, 7, 8

## SKRWAEE030
designator S?
3.7X3.7mm TACT Switch
footprint SKRWAEE030
pins: 1, 2, 3, 4

## SKT_SMD
designator D?, comment SS14
Surface Mount Diode
footprint DIOM5326X230L (Diode with Molded Body)
footprint DIOM5326X230M (Diode with Molded Body)
footprint DIOM5326X230N (Diode with Molded Body)
footprint SOD3716X135L
footprint SOD3716X135M
footprint SOD3716X135N
footprint SOD-323 (SOD-323/SC-76; 2 Leads; Body 1.7 x 1.3 mm, (LxW))
footprint SOD2512X100L (SOD Diode: SOD-323)
footprint SOD2512X100M (SOD Diode: SOD-323)
footprint SOD2512X100N (SOD Diode: SOD-323)
footprint DIOM7959X241L (Diode with Molded Body DO-214AB, SMC)
footprint DIOM7959X241M (Diode with Molded Body DO-214AB, SMC)
footprint DIOM7959X241N (Diode with Molded Body DO-214AB, SMC)
footprint X1-DFN1006-2
pins: 1, 2

## SMF05C
designator D?
5-Line Transient Voltage Suppressor Array
footprint SOT363-6L (SOT363, 6-Leads, Body 2x1.3mm, Pitch 0.65mm, Lead Span 2.1mm, IPC High Density)
footprint SOT363-6M
footprint SOT363-6N (SOT363, 6-Leads, Body 2x1.3mm, Pitch 0.65mm, Lead Span 2.1mm, IPC Medium Density)
pins: 1 NC, 2 NC, 3 NC, 4 NC, 5 NC, 6 NC

## SMI-12VDC-SL-C
designator S?, comment SPDT Relay
Single Pole Doulbe Throw Relay
footprint SMI-12VDC-SL-C (SPDT Relay)
pins: 1, 2, 3, 4, 5

## SOIL_SENSOR
designator *
pins: 1, 2

## SOLDER_JUMPER
designator J?  (no BOM)
footprint SOLDER_JUMPER_HALF_CIRCLE
footprint SOLDER_JUMPER_RETANGULAR
footprint SOLDER_JUMPER_CIRCLE
footprint SOLDER_JUMPER_HALF_CIRCLE_0.5MM_OPEN
pins: 1, 2

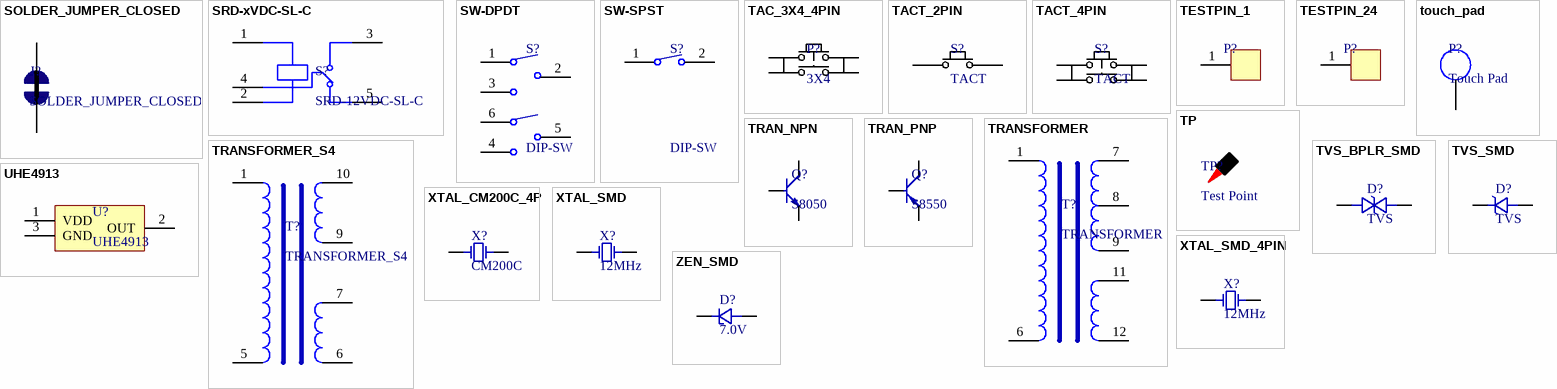
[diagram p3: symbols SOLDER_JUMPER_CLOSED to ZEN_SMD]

## SOLDER_JUMPER_CLOSED
designator J?  (no BOM)
footprint SOLDER_JUMPER_HALF_CIRCLE_0.5mm_CLOSED
pins: 1, 2

## SRD-xVDC-SL-C
designator S?, comment SRD-12VDC-SL-C
Single Pole Double Throw Relay
footprint SRD-xVDC-SL-C
pins: 1, 2, 3, 4, 5

## SW-DPDT
designator S?, comment DIP-SW
footprint DPDT-6PIN (Double-Pole, Double-Throw Switch; 6 Leads)
pins: 1, 2, 3, 4, 5, 6

## SW-SPST
designator S?, comment DIP-SW
footprint TACT_SIDE (Tact Switch Side Push)
footprint TACT_TOP (Tact Switch Side Push)
footprint TACT_RECT
footprint TACT_3X3
footprint KAN-15
pins: 1, 2

## TAC_3X4_4PIN
designator P?, comment 3X4
footprint TACT_3X4_4PIN
pins: 1, 2, 3, 4

## TACT_2PIN
designator S?, comment TACT
footprint TACT_3X4
footprint TACT_3X4_NMH
footprint TACT_3X6
footprint TACT_SIDE_45X45
pins: 1, 2

## TACT_4PIN
designator S?, comment TACT
footprint TACT_3X3
footprint TACT_4X4
footprint TACT_TOP (Tact Switch Side Push)
pins: 1, 2, 3, 4

## TESTPIN_1
designator P?, comment TESTPIN  (value not drawn)
footprint TESTPIN_24
footprint TESTPIN_1mm
pins: 1

## TESTPIN_24
designator P?, comment TESTPIN  (value not drawn)
footprint TESTPIN_24
pins: 1

## touch_pad
designator P?, comment Touch Pad
footprint TOUCHPAD100X500
footprint TOUCHPAD_TH
pins: 1 PAD

## TP
designator TP?, comment Test Point
footprint TP_TH_10_20
footprint TP_SMT_10
footprint 5016
footprint TP_SMD_35MIL
footprint TP_SMT_20
pins: 1

## TRAN_NPN
designator Q?, comment S8050
Surface Mount NPN Transistor
footprint SOT23-3L (SOT23, 3-Leads, Body 2.9x1.3mm, Pitch 0.95mm, Lead Span 2.5mm, IPC High Density)
footprint SOT23-3M (SOT23, 3-Leads, Body 2.9x1.3mm, Pitch 0.95mm, Lead Span 2.5mm, IPC Low Density)
footprint SOT23-3N (SOT23, 3-Leads, Body 2.9x1.3mm, Pitch 0.95mm, Lead Span 2.5mm, IPC Medium Density)
pins: 1, 2, 3

## TRAN_PNP
designator Q?, comment S8550
Surface Mount NPN Transistor
footprint SOT23-3L (SOT23, 3-Leads, Body 2.9x1.3mm, Pitch 0.95mm, Lead Span 2.5mm, IPC High Density)
footprint SOT23-3M (SOT23, 3-Leads, Body 2.9x1.3mm, Pitch 0.95mm, Lead Span 2.5mm, IPC Low Density)
footprint SOT23-3N (SOT23, 3-Leads, Body 2.9x1.3mm, Pitch 0.95mm, Lead Span 2.5mm, IPC Medium Density)
pins: 1, 2, 3

## TRANSFORMER
designator T?
POWER LINE TRANSFORMER
footprint TRANSFORMER_S8
pins: 1, 6, 7, 8, 9, 11, 12

## TRANSFORMER_S4
designator T?
POWER LINE TRANSFORMER
footprint TRANSFORMER_S4
pins: 1, 5, 6, 7, 9, 10

## TVS_BPLR_SMD
designator D?, comment TVS
Transient Voltage Suppressor
footprint DIOM7959X241L (Diode with Molded Body DO-214AB, SMC)
footprint DIOM7959X241M (Diode with Molded Body DO-214AB, SMC)
footprint DIOM7959X241N (Diode with Molded Body DO-214AB, SMC)
footprint SOD-323 (SOD-323/SC-76; 2 Leads; Body 1.7 x 1.3 mm, (LxW))
footprint DIOM5326X230N (Diode with Molded Body DO-214AC,SMA)
footprint DIOM5326X230L (Diode with Molded Body, DO-214AC,SMA)
footprint DIOM5326X230M (Diode with Molded Body. DO-214AC, SMA)
pins: 1, 2

## TVS_SMD
designator D?, comment TVS
Transient Voltage Suppressor
footprint DIOM7959X241L (Diode with Molded Body DO-214AB, SMC)
footprint DIOM7959X241M (Diode with Molded Body DO-214AB, SMC)
footprint DIOM7959X241N (Diode with Molded Body DO-214AB, SMC)
footprint SOD-323 (SOD-323/SC-76; 2 Leads; Body 1.7 x 1.3 mm, (LxW))
footprint DIOM5326X230N (Diode with Molded Body DO-214AC,SMA)
footprint DIOM5326X230L (Diode with Molded Body, DO-214AC,SMA)
footprint DIOM5326X230M (Diode with Molded Body. DO-214AC, SMA)
footprint SOD-523 (1.2x0.8X0.6mm（长宽高，不包括引脚）)
footprint SOD3716X135L (SOD Diode: SOD-123)
footprint SOD3716X135M (SOD Diode: SOD-123)
footprint SOD3716X135N (SOD Diode: SOD-123)
footprint DIOM5336X240L (Diode with Molded Body DO-214AA, SMB)
footprint DIOM5336X240M (Diode with Molded Body DO-214AA, SMB)
footprint DIOM5336X240N (Diode with Molded Body DO-214AA, SMB)
pins: 1, 2

## UHE4913
designator U?
LOW POWER HALL EFFECT  SWITCH
footprint SOT23-3N (SOT23, 3-Leads, Body 2.9x1.3mm, Pitch 0.95mm, Lead Span 2.5mm, IPC Medium Density)
footprint SOT23-3M (SOT23, 3-Leads, Body 2.9x1.3mm, Pitch 0.95mm, Lead Span 2.5mm, IPC Low Density)
footprint SOT23-3L (SOT23, 3-Leads, Body 2.9x1.3mm, Pitch 0.95mm, Lead Span 2.5mm, IPC High Density)
pins: 1 VDD, 2 OUT, 3 GND

## XTAL_CM200C_4P
designator X?, comment CM200C
Citizen Crystal
footprint CM200C (CITIZEN 4-PIN CRYSTAL)
pins: 1, 2 (power) hidden, 3 (power) hidden, 4

## XTAL_SMD
designator X?, comment 12MHz
Surface Mount Crystal
footprint XTAL1140X480L (SMD Crystal)
footprint XTAL1140X480M (SMD Crystal)
footprint XTAL1140X480N (SMD Crystal)
footprint ABS06-107-32.768kHz-T (SMD Low ESR Crystal)
footprint XTAL500X320
pins: 1, 2

## XTAL_SMD_4PIN
designator X?, comment 12MHz
Surface Mount Crystal
footprint OSCCC250X320X100L
footprint OSCCC250X320X100M
footprint OSCCC250X320X100N
footprint OSCCC320X500X150L
footprint OSCCC320X500X150M
footprint OSCCC320X500X150N
footprint OSCCC200X250X100
footprint OSCCC160X200X100
pins: 1, 2 hidden to GND, 3, 4 hidden to GND

## ZEN_SMD
designator D?, comment 7.0V
Surface Mount Zener Diode
footprint DIOM5326X230L (Diode with Molded Body)
footprint DIOM5326X230M (Diode with Molded Body)
footprint DIOM5326X230N (Diode with Molded Body)
footprint SOD3716X135L (SOD Diode: SOD-123)
footprint SOD3716X135M (SOD Diode: SOD-123)
footprint SOD3716X135N (SOD Diode: SOD-123)
footprint SOD-323 (SOD-323/SC-76; 2 Leads; Body 1.7 x 1.3 mm, (LxW))
pins: 1, 2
